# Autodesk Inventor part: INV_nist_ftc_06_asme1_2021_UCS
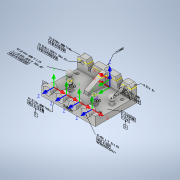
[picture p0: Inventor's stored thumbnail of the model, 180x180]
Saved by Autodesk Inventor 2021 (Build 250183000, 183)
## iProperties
Created: 2016-11
Part Number: INV_nist_ftc_06_asme1_2021_UCS
Material: Generic
Document SubType Name: Modeling
Designer: t_liuje
Density: 1 g/cm^3
Appearance: Default
Author: t_liuje
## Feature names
1. Extrusion1
2. Extrusion2
3. Extrusion3
4. Revolution1
5. Rectangular Pattern1
6. Loft1
7. Extrusion4
8. Hole13
9. Hole3
10. Hole8
11. Extrusion7
12. Hole4
13. Fillet2
14. Revolution2
15. Extrusion5
16. Hole6
17. Mirror2
18. Fillet4
19. Hole9
20. Hole10
21. Hole11
22. Hole12
## Parameters: d0 = 31.75 mm, d1 = 31.75 mm, d2 = 25.4 mm, d3 = 234.95 mm, d4 = 50.8 mm, d5 = 97.79 mm, d6 = 304.8 mm, d7 = 0, d9 = 15.24 mm, d10 = 2.54 mm, d11 = 25.4 mm, d12 = 0, d13 = 0, d14 = 2.54 mm, d15 = 2.54 mm, d16 = 115 deg, d17 = 115 deg, d18 = 63.5 mm, d19 = 13.97 mm, d20 = 12.7 mm, d21 = 31.75 mm, d22 = 25.4 mm, d23 = 0, d25 = 31.75 mm, d28 = 82.55 mm, d29 = 76.2 mm, d30 = 15.24 mm, d31 = 0, d35 = -31.75 mm, d39 = 96.52 mm, d40 = 11.43 mm, d41 = 31.75 mm, d42 = 31.75 mm, d43 = 90 deg, d44 = 38.1 mm, d45 = 19.05 mm, d46 = 0, d47 = 90 deg, d48 = 0, d49 = 90 deg, d50 = 44.45 mm, d51 = 44.45 mm, d52 = 50.8 mm, d53 = 50.8 mm, d54 = 43.815 mm, d55 = 72.39 mm, d56 = 38.1 mm, d57 = 0, d58 = 25.4 mm, d59 = 25.4 mm, d76 = 21.59 mm, d77 = 28.575 mm, d78 = 14.2748 mm, d79 = 19.05 mm, d80 = 20.6248 mm, d81 = 17.526 mm, d82 = 82 deg, d83 = 25.4 mm, d84 = 0, d85 = 25.4 mm, d86 = 57.15 mm, d87 = 10.541 mm, d88 = 19.05 mm, d89 = 15.875 mm, d90 = 12.7 mm, d91 = 82 deg, d92 = 31.75 mm, d93 = 0, d104 = 12.7 mm, d106 = 25.4 mm, d109 = 90 deg, d269 = 6.35 mm, d270 = 124.46 mm, d271 = 2.54 mm, d272 = 0, d436 = 25.4 mm, d437 = 25.4 mm, d413 = 6.35 mm, d414 = 19.05 mm, d415 = 9.525 mm, d416 = 6.35 mm, d417 = 82 deg, d418 = 12.7 mm, d419 = 118 deg, d477 = -19.05 mm, d478 = 25.4 mm, d479 = 25.4 mm, d532 = 152.4 mm, d533 = 38.1 mm, d534 = 0, d535 = 90 deg, d536 = 0, d537 = 180 deg, d543 = 0, d544 = 0, d545 = 0, d546 = 90 deg, d547 = 0, d548 = 180 deg, d570 = 0, d571 = 0, d572 = -6.35 mm, d573 = 90 deg, d574 = 0, d575 = 180 deg, d813 = 241.3 mm, d814 = 20.6248 mm, d815 = 19.05 mm, d816 = 9.525 mm, d817 = 6.35 mm, d818 = 82 deg, d819 = 14.224 mm, d820 = 0, d821 = 0, d822 = 0, d824 = 3.175 mm, d825 = 10.16 mm, d826 = 19.05 mm, d827 = 9.525 mm, d828 = 6.35 mm, d829 = 82 deg, d830 = 7.874 mm, d831 = 0, d832 = 10.16 mm, d833 = 19.05 mm, d834 = 9.525 mm, d835 = 6.35 mm, d836 = 82 deg, d837 = 7.874 mm, d838 = 0, d839 = 10.16 mm, d840 = 19.05 mm, d841 = 9.525 mm, d842 = 6.35 mm, d843 = 82 deg, d844 = 7.874 mm, d845 = 0, d846 = 10.16 mm, d847 = 19.05 mm, d848 = 9.525 mm, d849 = 6.35 mm, d850 = 82 deg, d851 = 7.874 mm, d852 = 0, d916 = 7.1374 mm, d917 = 19.05 mm, d918 = 9.525 mm, d919 = 6.35 mm, d920 = 82 deg, d921 = 25.4 mm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
